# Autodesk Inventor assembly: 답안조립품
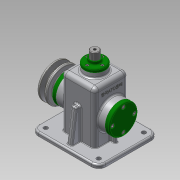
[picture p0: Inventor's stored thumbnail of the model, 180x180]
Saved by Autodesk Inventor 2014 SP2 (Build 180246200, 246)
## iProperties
Created: 2016-08
Part Number: 답안조립품
Document SubType Name: Assembly
Designer: 402-32
Author: 402-32
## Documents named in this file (19)
- C:\Users\402-32\Desktop\460820V1016\답안조립품.iam
- C:\Users\402-32\Desktop\460820V1016\본체.ipt
- C:\Users\402-32\Desktop\460820V1016\베어링 15 x 35 x 11.ipt
- C:\Users\402-32\Desktop\460820V1016\편심축.ipt
- C:\Users\402-32\Desktop\460820V1016\멈춤링 15 x 1.ipt
- C:\Users\402-32\Desktop\460820V1016\뒤커버.ipt
- C:\Users\402-32\Desktop\460820V1016\앞커버.ipt
- C:\Users\402-32\Desktop\460820V1016\볼트 M4 x 10.ipt
- C:\Users\402-32\Desktop\460820V1016\오일실 15 25 7.ipt
- C:\Users\402-32\Desktop\460820V1016\키 5 x 5 x 14.ipt
- C:\Users\402-32\Desktop\460820V1016\V-벨트풀리.ipt
- C:\Users\402-32\Desktop\460820V1016\와셔.ipt
- C:\Users\402-32\Desktop\460820V1016\볼트 M6 x 12.ipt
- C:\Users\402-32\Desktop\460820V1016\링크.ipt
- C:\Users\402-32\Desktop\460820V1016\슬라이드바.ipt
- C:\Users\402-32\Desktop\460820V1016\고정핀.ipt
- C:\Users\402-32\Desktop\460820V1016\멈춤링 6 x 5.ipt
- C:\Users\402-32\Desktop\460820V1016\상부부시.ipt
- C:\Users\402-32\Desktop\460820V1016\볼트 M3 x 8.ipt
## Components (15 placed, 5 different names)
1. ISO 4762 M4 x 10:6
2. ISO 4762 M4 x 10:7
3. ISO 4762 M4 x 10:8
4. ISO 4762 M4 x 10:9
5. V-벨트풀리:1 — 각도:1
6. ISO 4018 M6 x 12:1 — 강체:5
7. 고정핀:1
8. ISO 4762 M4 x 10:1 — 강체:3
9. ISO 4762 M4 x 10:3
10. ISO 4762 M4 x 10:4
11. ISO 4762 M4 x 10:5
12. ISO 4762 M3 x 8:1 — 강체:6
13. ISO 4762 M3 x 8:2
14. ISO 4762 M3 x 8:3
15. ISO 4762 M3 x 8:4
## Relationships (4: WeldJoint 3, Angle 1)
- 강체:3 [WeldJoint]: ISO 4762 M4 x 10:1
- 각도:1 [Angle]: V-벨트풀리:1
- 강체:5 [WeldJoint]: ISO 4018 M6 x 12:1
- 강체:6 [WeldJoint]: ISO 4762 M3 x 8:1
